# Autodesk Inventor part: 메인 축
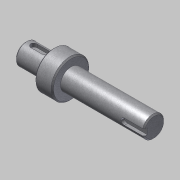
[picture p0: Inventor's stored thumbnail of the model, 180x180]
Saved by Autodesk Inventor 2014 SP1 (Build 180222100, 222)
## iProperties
Created: 2016-04
Part Number: 메인 축
Document SubType Name: Modeling
Designer: mdu
Density: 7.86 g/cm^3
Mass: 230.24 g
Surface Area: 74.3518 cm^2
Volume: 29.2926 cm^3
Material: 강철, 연강
Appearance: 금속-강(스테인리스, 브러시됨)
Author: mdu
Revision Number: 1
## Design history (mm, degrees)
sketch "스케치1"
  geometry: L1 (10.497, -57.5)-(112.497, -57.5); L2 (10.497, -66)-(32.497, -66); L3 (32.497, -72.5)-(46.5, -72.5); L4 (46.5, -66)-(112.497, -66); L5 (112.497, -66)-(112.497, -57.5); L6 (10.497, -66)-(10.497, -57.5); L7 (46.5, -69.749)-(46.5, -45.251) reference; L8 (46.5, -72.5)-(46.5, -66); L9 (32.497, -72.5)-(32.497, -66); L10 (32.497, -35)-(32.497, -80) reference; 3 further points
  constraints: 16 end point, 3 point on line, 2 parallel, 2 perpendicular, 1 collinear, 1 horizontal, 1 midpoint
  dimensions: "d0" = 17 diameter of L4 L1; "d1" = 30 diameter of L3 L1; "d2" = 22 distance of L2.start L2.end; "d3" = 65.99692 distance of L4.start L4.end (derived); "d5" = 17 diameter of L2 L1; "d19" = 80 distance between parallel lines of L5 L9
revolve "회전1" sketch "스케치1" stored, may be unused: angle "d4" = 90 deg
chamfer "모따기1" distance "d6" = 1; stored, may be unused: second distance "d7" = 2, angle "d8" = 45 deg
node "작업 평면1"
sketch "스케치2"
  geometry: L1 (-11, -7.5)-(-11, 7.5) reference; L2 (-4.5, 2.5)-(4.5, 2.5); L3 (4.5, -2.5)-(-4.5, -2.5); A1 r 2.5 centre (4.5, 0) between (4.5, -2.5) and (4.5, 2.5); A2 r 2.5 centre (-4.5, 0) between (-4.5, 2.5) and (-4.5, -2.5); 2 further points
  constraints: 4 end point, 4 point on circle, 4 tangent, 2 centre point, 1 horizontal alignment, 1 midpoint, 1 parallel, 1 perpendicular
  dimensions: "d9" = 5 distance between parallel lines of L3 L2; "d10" = 14 dimension on A1 A2; "d11" = 4 distance edge to line of A2 L1
extrude "돌출1" cut sketch "스케치2" distance "d12" = 3; taper "d13" = 0 deg
node "작업 평면2"
sketch "스케치3"
  geometry: L1 (32.998, 7.5)-(32.998, -7.5) reference; L2 (32.998, 2.5)-(17.498, 2.5); L3 (17.498, -2.5)-(32.998, -2.5); A1 r 2.5 centre (17.498, 0) between (17.498, 2.5) and (17.498, -2.5); 2 further points
  constraints: 4 end point, 2 perpendicular, 2 point on circle, 2 point on line, 2 tangent, 1 centre point, 1 horizontal alignment, 1 midpoint
  dimensions: "d14" = 5 distance between parallel lines of L3 L2; "d15" = 18 dimension on A1 L1
extrude "돌출2" cut sketch "스케치3" distance "d16" = 3; taper "d17" = 0 deg
node "솔리드1"
node "참조4"
node "참조5"
